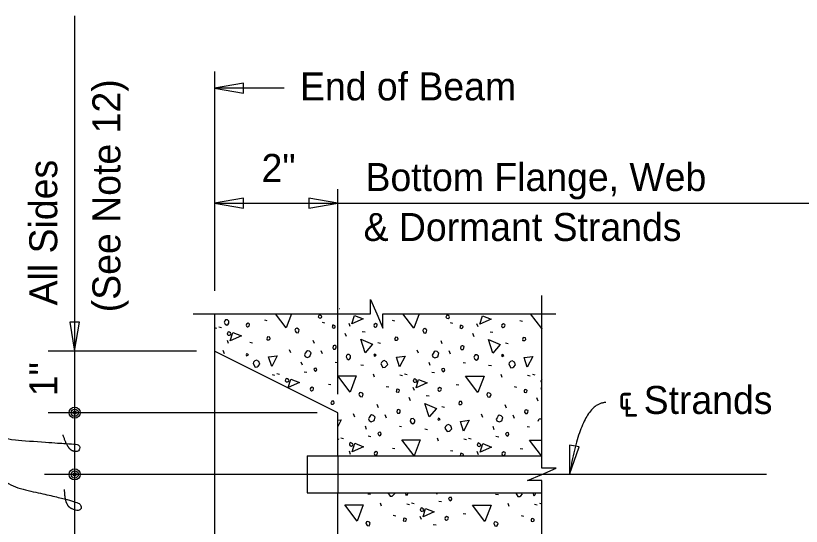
# Model space of a CAD drawing. Extents: x 0.5 to 29.5, y 0.9 to 17.7.
# Drawn here: x 2.752 to 7.001, y 2.834 to 5.592 of the extents above; entities that cross this region are included whole.
import ezdxf

# ---------------------------------------------------------------- set-up
doc = ezdxf.new("R2010")
doc.units = 0
for name, color, linetype in [('BeamConc', 7, 'Continuous'), ('BeamConc_h', 7, 'Continuous'), ('CL_Major', 7, 'Continuous'), ('Dimension', 7, 'Continuous'), ('Miscellaneous', 7, 'Continuous'), ('Rebar', 7, 'Continuous'), ('TextStructures', 7, 'Continuous')]:
    doc.layers.add(name, color=color, linetype=linetype)

msp = doc.modelspace()

# ---------------------------------------------------------------- linework, layer by layer
at = {"layer": 'BeamConc'}
for p, q in [((3.8274, 3.9817), (3.8274, 2.2462)), ((4.4941, 3.4472), (3.8274, 3.7806)), ((4.4941, 3.2139), (4.4941, 3.4472)), ((4.4941, 2.7806), (4.4941, 3.0139))]:
    msp.add_line(p, q, dxfattribs=at)
at = {"layer": 'BeamConc_h'}
msp.add_line((4.4941, 3.2139), (4.4941, 3.0139), dxfattribs=at)
at = {"layer": 'CL_Major'}
msp.add_line((6.8131, 3.1139), (2.9073, 3.1139), dxfattribs=at)
at = {"layer": 'Dimension'}
for p, q in [((3.0702, 5.5924), (3.0702, 2.0646)), ((3.8274, 5.2914), (3.8274, 4.1065)), ((4.2039, 5.2011), (3.8274, 5.2011)), ((4.4941, 3.5472), (4.4941, 4.6553)), ((3.8274, 4.5797), (7.089, 4.5797)), ((3.7295, 3.7806), (2.9278, 3.7806)), ((4.3815, 3.4472), (2.9278, 3.4472))]:
    msp.add_line(p, q, dxfattribs=at)
for points in [[(3.8273, 5.2012), (3.9835, 5.1747), (3.9835, 5.2276)], [(3.8273, 4.5797), (3.9835, 4.5532), (3.9835, 4.6062)], [(4.494, 4.5797), (4.3378, 4.6062), (4.3378, 4.5532)], [(3.0701, 3.7806), (3.0966, 3.9368), (3.0436, 3.9368)], [(5.7476, 3.1137), (5.7988, 3.2636), (5.7466, 3.2721)]]:
    msp.add_lwpolyline(points, close=True, dxfattribs=at)
for points in [[(5.5975, 2.1704), (5.5975, 3.0802), (5.52, 3.0802), (5.5975, 3.114), (5.675, 3.1477), (5.5975, 3.1477), (5.5975, 4.0806)], [(3.711, 3.9817), (4.6705, 3.9817), (4.6705, 4.0592), (4.7042, 3.9817), (4.738, 3.9042), (4.738, 3.9817), (5.6732, 3.9817)]]:
    msp.add_lwpolyline(points, dxfattribs=at)
for centre, radius in [((3.0707, 3.4475), 0.0299), ((3.0707, 3.4475), 0.0196), ((3.0707, 3.4475), 0.00888), ((3.0707, 3.1139), 0.0299), ((3.0707, 3.1139), 0.0196), ((3.0707, 3.1139), 0.00888)]:
    msp.add_circle(centre, radius, dxfattribs=at)
for points in [[(2.5377, 3.5116), (2.5377, 3.087), (3.0741, 2.9719), (3.1137, 2.9408), (3.0911, 2.9104), (3.0163, 2.9472), (3.0163, 3.0319)], [(5.9432, 3.5021), (5.8108, 3.5021), (5.7476, 3.1137)], [(2.538, 3.4819), (2.538, 3.3138), (3.0529, 3.2785), (3.1011, 3.2749), (3.0939, 3.2311), (3.0319, 3.248), (3.0079, 3.3286)]]:
    msp.add_open_spline(points, degree=2, dxfattribs=at)
at = {"layer": 'Miscellaneous'}
for p, q in [((4.5038, 4.0107), (4.5044, 4.0106)), ((3.8499, 3.9113), (3.864, 3.9078)), ((4.0965, 3.9487), (4.1098, 3.946)), ((4.4094, 3.9363), (4.4227, 3.9337)), ((4.5615, 3.9133), (4.5553, 3.9301)), ((4.7877, 3.9469), (4.801, 3.9443)), ((5.1006, 3.9346), (5.1139, 3.9319)), ((5.2527, 3.9116), (5.2465, 3.9284)), ((5.4789, 3.9452), (5.4922, 3.9425)), ((3.8243, 3.9069), (3.8384, 3.9033)), ((4.5402, 3.8585), (4.5332, 3.8762)), ((4.626, 3.8859), (4.6419, 3.8842)), ((5.2314, 3.8568), (5.2244, 3.8745)), ((5.3172, 3.8842), (5.3331, 3.8824)), ((3.9029, 3.8211), (3.8967, 3.8379)), ((4.0188, 3.8285), (4.0329, 3.825)), ((4.3679, 3.8205), (4.3608, 3.8382)), ((4.71, 3.8267), (4.7241, 3.8232)), ((5.0591, 3.8188), (5.052, 3.8364)), ((5.4012, 3.825), (5.4153, 3.8214)), ((3.8817, 3.7663), (3.8746, 3.784)), ((4.2397, 3.7702), (4.2327, 3.7878)), ((4.4112, 3.7649), (4.4041, 3.7825)), ((4.9309, 3.7684), (4.9239, 3.7861)), ((5.1024, 3.7631), (5.0953, 3.7808)), ((4.3025, 3.7039), (4.2963, 3.7207)), ((4.4801, 3.7207), (4.4925, 3.7189)), ((4.618, 3.7065), (4.6331, 3.7039)), ((4.9937, 3.7021), (4.9875, 3.7189)), ((5.1713, 3.7189), (5.1837, 3.7171)), ((5.3092, 3.7047), (5.3243, 3.7021)), ((4.1381, 3.6544), (4.1522, 3.6508)), ((4.1637, 3.6588), (4.1779, 3.6553)), ((4.3113, 3.6685), (4.3263, 3.6659)), ((4.6923, 3.6393), (4.6861, 3.6561)), ((4.8549, 3.657), (4.8691, 3.6535)), ((5.0025, 3.6667), (5.0175, 3.6641)), ((5.3835, 3.6376), (5.3773, 3.6544)), ((5.5461, 3.6553), (5.5602, 3.6517)), ((4.8293, 3.6526), (4.8434, 3.6491)), ((5.5205, 3.6508), (5.5346, 3.6473)), ((4.443, 3.6022), (4.4563, 3.5996)), ((4.7559, 3.5898), (4.7692, 3.5872)), ((4.9079, 3.5669), (4.9018, 3.5837)), ((5.1342, 3.6005), (5.1475, 3.5978)), ((5.4471, 3.5881), (5.4604, 3.5854)), ((5.5975, 3.5694), (5.593, 3.5819)), ((4.8867, 3.5121), (4.8797, 3.5297)), ((4.9725, 3.5395), (4.9884, 3.5377)), ((5.5779, 3.5103), (5.5709, 3.528)), ((4.7144, 3.4741), (4.7073, 3.4917)), ((5.4056, 3.4723), (5.3985, 3.49)), ((5.0564, 3.4802), (5.0706, 3.4767)), ((4.5862, 3.4237), (4.5791, 3.4414)), ((4.7577, 3.4184), (4.7506, 3.436)), ((5.2774, 3.4219), (5.2703, 3.4396)), ((5.4489, 3.4166), (5.4418, 3.4343)), ((4.649, 3.3574), (4.6428, 3.3742)), ((4.8266, 3.3742), (4.839, 3.3724)), ((4.9645, 3.36), (4.9795, 3.3574)), ((5.3402, 3.3556), (5.334, 3.3724)), ((5.5178, 3.3724), (5.5302, 3.3706)), ((4.6578, 3.322), (4.6728, 3.3194)), ((5.349, 3.3203), (5.364, 3.3176)), ((4.4941, 3.3055), (4.4987, 3.3044)), ((4.5102, 3.3123), (4.5243, 3.3088)), ((5.0388, 3.2929), (5.0326, 3.3097)), ((5.1758, 3.3061), (5.1899, 3.3026)), ((5.2014, 3.3105), (5.2155, 3.307)), ((4.5632, 3.2221), (4.557, 3.2389)), ((4.7895, 3.2557), (4.8028, 3.2531)), ((5.1024, 3.2434), (5.1157, 3.2407)), ((5.2544, 3.2204), (5.2482, 3.2372)), ((5.4807, 3.254), (5.494, 3.2513)), ((4.656, 3.0096), (4.671, 3.007)), ((5.0316, 3.0052), (5.0284, 3.0139)), ((5.3472, 3.0078), (5.3622, 3.0052)), ((4.7302, 2.9424), (4.724, 2.9592)), ((4.8672, 2.9557), (4.8814, 2.9522)), ((4.8929, 2.9601), (4.907, 2.9566)), ((5.0405, 2.9698), (5.0555, 2.9672)), ((5.4214, 2.9407), (5.4152, 2.9575)), ((5.5584, 2.9539), (5.5726, 2.9504)), ((5.584, 2.9583), (5.5976, 2.955)), ((4.4941, 2.9027), (4.4942, 2.9027)), ((4.7939, 2.8929), (4.8071, 2.8903)), ((5.1722, 2.9035), (5.1854, 2.9009)), ((5.4851, 2.8912), (5.4983, 2.8885)), ((4.9459, 2.87), (4.9397, 2.8868)), ((5.0104, 2.8426), (5.0263, 2.8408))]:
    msp.add_line(p, q, dxfattribs=at)
for points in [[(4.2141, 3.9054), (4.1561, 3.9817)], [(4.2426, 3.9817), (4.2141, 3.9054)], [(4.393, 3.9593), (4.3992, 3.9584), (4.4054, 3.9611), (4.4072, 3.9664), (4.4045, 3.9708), (4.3992, 3.9743), (4.393, 3.977), (4.3895, 3.9699), (4.3877, 3.9646), (4.393, 3.9593)], [(4.5703, 3.9275), (4.5844, 3.9734), (4.6313, 3.9549), (4.5703, 3.9275)], [(4.9053, 3.9036), (4.846, 3.9817)], [(4.9345, 3.9817), (4.9053, 3.9036)], [(5.0842, 3.9575), (5.0904, 3.9567), (5.0966, 3.9593), (5.0984, 3.9646), (5.0957, 3.969), (5.0904, 3.9726), (5.0842, 3.9752), (5.0807, 3.9681), (5.0789, 3.9628), (5.0842, 3.9575)], [(5.2615, 3.9257), (5.2756, 3.9717), (5.3225, 3.9531), (5.2615, 3.9257)], [(5.5965, 3.9019), (5.5358, 3.9817)], [(3.88, 3.9364), (3.8853, 3.9258), (3.8941, 3.9205), (3.9012, 3.9258), (3.9047, 3.9311), (3.9047, 3.9417), (3.8967, 3.9497), (3.887, 3.9488), (3.8826, 3.9444), (3.88, 3.9364)], [(4.0028, 3.9116), (4.0064, 3.9116), (4.0135, 3.9151), (4.0161, 3.9231), (4.0152, 3.9275), (4.0081, 3.931), (3.9993, 3.9257), (3.9975, 3.9204), (3.9993, 3.9151), (4.0028, 3.9116)], [(4.4633, 3.9072), (4.4731, 3.9045), (4.4793, 3.9089), (4.4801, 3.9151), (4.4784, 3.9169), (4.4713, 3.9204), (4.4651, 3.9195), (4.4642, 3.9133), (4.4633, 3.9072)], [(4.694, 3.9098), (4.6976, 3.9098), (4.7047, 3.9133), (4.7073, 3.9213), (4.7064, 3.9257), (4.6993, 3.9293), (4.6905, 3.924), (4.6887, 3.9186), (4.6905, 3.9133), (4.694, 3.9098)], [(5.1545, 3.9054), (5.1643, 3.9027), (5.1705, 3.9072), (5.1713, 3.9133), (5.1696, 3.9151), (5.1625, 3.9186), (5.1563, 3.9178), (5.1554, 3.9116), (5.1545, 3.9054)], [(5.3852, 3.908), (5.3888, 3.908), (5.3958, 3.9116), (5.3985, 3.9195), (5.3976, 3.924), (5.3905, 3.9275), (5.3817, 3.9222), (5.3799, 3.9169), (5.3817, 3.9116), (5.3852, 3.908)], [(3.9012, 3.8671), (3.9074, 3.8662), (3.9135, 3.8689), (3.9153, 3.8742), (3.9127, 3.8786), (3.9074, 3.8821), (3.9012, 3.8848), (3.8976, 3.8777), (3.8959, 3.8724), (3.9012, 3.8671)], [(3.9118, 3.8353), (3.9259, 3.8812), (3.9728, 3.8627), (3.9118, 3.8353)], [(4.2636, 3.8895), (4.268, 3.8815), (4.2786, 3.8798), (4.283, 3.8877), (4.2848, 3.8948), (4.2804, 3.8992), (4.2724, 3.9036), (4.2645, 3.901), (4.2618, 3.893), (4.2636, 3.8895)], [(4.9548, 3.8877), (4.9592, 3.8798), (4.9698, 3.878), (4.9742, 3.8859), (4.976, 3.893), (4.9716, 3.8974), (4.9636, 3.9019), (4.9557, 3.8992), (4.953, 3.8912), (4.9548, 3.8877)], [(5.5976, 3.9047), (5.5965, 3.9019)], [(4.1124, 3.8409), (4.1231, 3.8409), (4.1284, 3.8462), (4.1257, 3.8559), (4.1142, 3.8568), (4.1124, 3.8515), (4.1098, 3.8471), (4.1124, 3.8409), (4.1107, 3.8426)], [(4.6419, 3.771), (4.618, 3.8444), (4.6808, 3.817), (4.6419, 3.771)], [(4.8036, 3.8391), (4.8143, 3.8391), (4.8196, 3.8444), (4.8169, 3.8541), (4.8054, 3.855), (4.8036, 3.8497), (4.801, 3.8453), (4.8036, 3.8391), (4.8019, 3.8409)], [(5.3331, 3.7693), (5.3092, 3.8426), (5.372, 3.8152), (5.3331, 3.7693)], [(5.4948, 3.8373), (5.5054, 3.8373), (5.5108, 3.8426), (5.5081, 3.8524), (5.4966, 3.8532), (5.4948, 3.8479), (5.4922, 3.8435), (5.4948, 3.8373), (5.4931, 3.8391)], [(4.3166, 3.7516), (4.3281, 3.7454), (4.3431, 3.7516), (4.3493, 3.7702), (4.3405, 3.779), (4.329, 3.7816), (4.3237, 3.7781), (4.3175, 3.7684), (4.3131, 3.7604), (4.3166, 3.7516)], [(4.466, 3.7984), (4.4704, 3.7905), (4.4801, 3.7914), (4.4846, 3.7976), (4.4854, 3.8073), (4.4793, 3.8099), (4.4748, 3.8108), (4.4695, 3.809), (4.4678, 3.8073), (4.466, 3.7984)], [(5.1572, 3.7967), (5.1616, 3.7887), (5.1713, 3.7896), (5.1758, 3.7958), (5.1766, 3.8055), (5.1705, 3.8082), (5.166, 3.809), (5.1607, 3.8073), (5.159, 3.8055), (5.1572, 3.7967)], [(4.0002, 3.7551), (4.0099, 3.7596), (4.0064, 3.7631), (4.0002, 3.7657), (3.9975, 3.7596), (4.0002, 3.7551)], [(4.1363, 3.6968), (4.1195, 3.7489), (4.1664, 3.7551), (4.1363, 3.6968)], [(4.5385, 3.7489), (4.5438, 3.7383), (4.5526, 3.733), (4.5597, 3.7383), (4.5632, 3.7436), (4.5632, 3.7542), (4.5553, 3.7622), (4.5456, 3.7613), (4.5411, 3.7569), (4.5385, 3.7489)], [(4.6914, 3.7534), (4.7011, 3.7578), (4.6976, 3.7613), (4.6914, 3.764), (4.6887, 3.7578), (4.6914, 3.7534)], [(4.8275, 3.695), (4.8107, 3.7472), (4.8576, 3.7534), (4.8275, 3.695)], [(5.0078, 3.7498), (5.0193, 3.7436), (5.0343, 3.7498), (5.0405, 3.7684), (5.0317, 3.7772), (5.0202, 3.7799), (5.0149, 3.7763), (5.0087, 3.7666), (5.0043, 3.7587), (5.0078, 3.7498)], [(5.2297, 3.7472), (5.235, 3.7366), (5.2438, 3.7313), (5.2509, 3.7366), (5.2544, 3.7419), (5.2544, 3.7525), (5.2465, 3.7604), (5.2367, 3.7596), (5.2323, 3.7551), (5.2297, 3.7472)], [(5.3826, 3.7516), (5.3923, 3.756), (5.3888, 3.7596), (5.3826, 3.7622), (5.3799, 3.756), (5.3826, 3.7516)], [(5.5187, 3.6933), (5.5019, 3.7454), (5.5488, 3.7516), (5.5187, 3.6933)], [(4.0356, 3.7127), (4.047, 3.6941), (4.0585, 3.695), (4.063, 3.6994), (4.0727, 3.7092), (4.0665, 3.7242), (4.0541, 3.7313), (4.0453, 3.7277), (4.0382, 3.7207), (4.0356, 3.7127)], [(4.7267, 3.7109), (4.7382, 3.6924), (4.7497, 3.6933), (4.7541, 3.6977), (4.7639, 3.7074), (4.7577, 3.7224), (4.7453, 3.7295), (4.7365, 3.726), (4.7294, 3.7189), (4.7267, 3.7109)], [(5.4179, 3.7092), (5.4294, 3.6906), (5.4409, 3.6915), (5.4453, 3.6959), (5.4551, 3.7056), (5.4489, 3.7207), (5.4365, 3.7277), (5.4277, 3.7242), (5.4206, 3.7171), (5.4179, 3.7092)], [(4.367, 3.6747), (4.3723, 3.6694), (4.3776, 3.6729), (4.3811, 3.6782), (4.3794, 3.6871), (4.375, 3.688), (4.3688, 3.6871), (4.3635, 3.6818), (4.367, 3.6747)], [(5.0582, 3.6729), (5.0635, 3.6676), (5.0688, 3.6712), (5.0723, 3.6765), (5.0706, 3.6853), (5.0662, 3.6862), (5.06, 3.6853), (5.0547, 3.68), (5.0582, 3.6729)], [(4.215, 3.6146), (4.2212, 3.6137), (4.2274, 3.6164), (4.2291, 3.6217), (4.2265, 3.6261), (4.2212, 3.6296), (4.215, 3.6323), (4.2114, 3.6252), (4.2097, 3.6199), (4.215, 3.6146)], [(4.2256, 3.5828), (4.2397, 3.6287), (4.2866, 3.6102), (4.2256, 3.5828)], [(4.5606, 3.5589), (4.4934, 3.6473), (4.5933, 3.6464), (4.5606, 3.5589)], [(4.9062, 3.6128), (4.9124, 3.6119), (4.9185, 3.6146), (4.9203, 3.6199), (4.9177, 3.6243), (4.9124, 3.6279), (4.9062, 3.6305), (4.9026, 3.6234), (4.9009, 3.6181), (4.9062, 3.6128)], [(4.9168, 3.581), (4.9309, 3.627), (4.9778, 3.6084), (4.9168, 3.581)], [(5.2518, 3.5571), (5.1846, 3.6455), (5.2845, 3.6446), (5.2518, 3.5571)], [(5.5975, 3.6287), (5.5974, 3.6287), (5.5938, 3.6217), (5.5921, 3.6164), (5.5974, 3.6111)], [(4.3493, 3.5651), (4.3529, 3.5651), (4.3599, 3.5686), (4.3626, 3.5766), (4.3617, 3.581), (4.3546, 3.5845), (4.3458, 3.5792), (4.344, 3.5739), (4.3458, 3.5686), (4.3493, 3.5651)], [(4.8098, 3.5607), (4.8196, 3.558), (4.8257, 3.5624), (4.8266, 3.5686), (4.8249, 3.5704), (4.8178, 3.5739), (4.8116, 3.5731), (4.8107, 3.5669), (4.8098, 3.5607)], [(5.0405, 3.5633), (5.0441, 3.5633), (5.0511, 3.5669), (5.0538, 3.5748), (5.0529, 3.5792), (5.0458, 3.5828), (5.037, 3.5775), (5.0352, 3.5722), (5.037, 3.5669), (5.0405, 3.5633)], [(5.501, 3.5589), (5.5108, 3.5563), (5.5169, 3.5607), (5.5178, 3.5669), (5.5161, 3.5686), (5.509, 3.5722), (5.5028, 3.5713), (5.5019, 3.5651), (5.501, 3.5589)], [(5.5974, 3.6111), (5.5975, 3.611)], [(4.6101, 3.543), (4.6145, 3.535), (4.6251, 3.5333), (4.6295, 3.5412), (4.6313, 3.5483), (4.6269, 3.5527), (4.6189, 3.5571), (4.611, 3.5545), (4.6083, 3.5465), (4.6101, 3.543)], [(5.3013, 3.5412), (5.3057, 3.5333), (5.3163, 3.5315), (5.3207, 3.5395), (5.3225, 3.5465), (5.3181, 3.551), (5.3101, 3.5554), (5.3022, 3.5527), (5.2995, 3.5448), (5.3013, 3.5412)], [(4.4589, 3.4944), (4.4695, 3.4944), (4.4748, 3.4997), (4.4722, 3.5094), (4.4607, 3.5103), (4.4589, 3.505), (4.4563, 3.5006), (4.4589, 3.4944), (4.4572, 3.4962)], [(4.9884, 3.4246), (4.9645, 3.4979), (5.0273, 3.4705), (4.9884, 3.4246)], [(5.1501, 3.4926), (5.1607, 3.4926), (5.166, 3.4979), (5.1634, 3.5076), (5.1519, 3.5085), (5.1501, 3.5032), (5.1475, 3.4988), (5.1501, 3.4926), (5.1484, 3.4944)], [(4.8125, 3.452), (4.8169, 3.444), (4.8266, 3.4449), (4.831, 3.4511), (4.8319, 3.4608), (4.8257, 3.4634), (4.8213, 3.4643), (4.816, 3.4626), (4.8143, 3.4608), (4.8125, 3.452)], [(5.5037, 3.4502), (5.5081, 3.4422), (5.5178, 3.4431), (5.5222, 3.4493), (5.5231, 3.459), (5.5169, 3.4617), (5.5125, 3.4626), (5.5072, 3.4608), (5.5054, 3.459), (5.5037, 3.4502)], [(4.4941, 3.4062), (4.5128, 3.4086), (4.4941, 3.3722)], [(4.6631, 3.4051), (4.6746, 3.3989), (4.6896, 3.4051), (4.6958, 3.4237), (4.687, 3.4325), (4.6755, 3.4352), (4.6702, 3.4316), (4.664, 3.4219), (4.6596, 3.414), (4.6631, 3.4051)], [(4.885, 3.4025), (4.8903, 3.3919), (4.8991, 3.3866), (4.9062, 3.3919), (4.9097, 3.3972), (4.9097, 3.4078), (4.9018, 3.4157), (4.892, 3.4148), (4.8876, 3.4104), (4.885, 3.4025)], [(5.0379, 3.4069), (5.0476, 3.4113), (5.0441, 3.4148), (5.0379, 3.4175), (5.0352, 3.4113), (5.0379, 3.4069)], [(5.174, 3.3485), (5.1572, 3.4007), (5.204, 3.4069), (5.174, 3.3485)], [(5.3543, 3.4033), (5.3658, 3.3972), (5.3808, 3.4033), (5.387, 3.4219), (5.3782, 3.4307), (5.3667, 3.4334), (5.3614, 3.4299), (5.3552, 3.4201), (5.3508, 3.4122), (5.3543, 3.4033)], [(5.5975, 3.4094), (5.593, 3.414), (5.5832, 3.4131), (5.5788, 3.4086), (5.5762, 3.4007)], [(5.0732, 3.3645), (5.0847, 3.3459), (5.0962, 3.3468), (5.1006, 3.3512), (5.1104, 3.3609), (5.1042, 3.3759), (5.0918, 3.383), (5.083, 3.3795), (5.0759, 3.3724), (5.0732, 3.3645)], [(4.7135, 3.3282), (4.7188, 3.3229), (4.7241, 3.3264), (4.7276, 3.3318), (4.7259, 3.3406), (4.7214, 3.3415), (4.7153, 3.3406), (4.71, 3.3353), (4.7135, 3.3282)], [(5.4047, 3.3264), (5.41, 3.3211), (5.4153, 3.3247), (5.4188, 3.33), (5.4171, 3.3388), (5.4126, 3.3397), (5.4065, 3.3388), (5.4012, 3.3335), (5.4047, 3.3264)], [(4.5615, 3.2681), (4.5676, 3.2672), (4.5738, 3.2699), (4.5756, 3.2752), (4.573, 3.2796), (4.5676, 3.2831), (4.5615, 3.2858), (4.5579, 3.2787), (4.5562, 3.2734), (4.5615, 3.2681)], [(4.5721, 3.2363), (4.5862, 3.2823), (4.6331, 3.2637), (4.5721, 3.2363)], [(4.9059, 3.2139), (4.8399, 3.3008), (4.9398, 3.2999), (4.9076, 3.2139)], [(5.2527, 3.2663), (5.2588, 3.2655), (5.265, 3.2681), (5.2668, 3.2734), (5.2641, 3.2778), (5.2588, 3.2814), (5.2527, 3.284), (5.2491, 3.2769), (5.2474, 3.2716), (5.2527, 3.2663)], [(5.2633, 3.2345), (5.2774, 3.2805), (5.3243, 3.2619), (5.2633, 3.2345)], [(5.5958, 3.2139), (5.5311, 3.299), (5.5975, 3.2985)], [(4.6958, 3.2186), (4.6993, 3.2186), (4.7064, 3.2221), (4.7091, 3.2301), (4.7082, 3.2345), (4.7011, 3.2381), (4.6923, 3.2328), (4.6905, 3.2275), (4.6923, 3.2221), (4.6958, 3.2186)], [(5.387, 3.2168), (5.3905, 3.2168), (5.3976, 3.2204), (5.4003, 3.2283), (5.3994, 3.2328), (5.3923, 3.2363), (5.3835, 3.231), (5.3817, 3.2257), (5.3835, 3.2204), (5.387, 3.2168)], [(5.1694, 3.2139), (5.1722, 3.216), (5.1731, 3.2221), (5.1713, 3.2239), (5.1643, 3.2275), (5.1581, 3.2266), (5.1572, 3.2204), (5.1563, 3.2142)], [(5.1563, 3.2142), (5.1572, 3.2139)], [(4.7647, 3.0139), (4.7762, 2.9955), (4.7877, 2.9964), (4.7921, 3.0008), (4.8018, 3.0105), (4.8004, 3.0139)], [(4.8654, 2.9981), (4.8604, 3.0139)], [(4.8736, 3.0139), (4.8654, 2.9981)], [(5.0961, 2.976), (5.1014, 2.9707), (5.1067, 2.9743), (5.1103, 2.9796), (5.1085, 2.9884), (5.1041, 2.9893), (5.0979, 2.9884), (5.0926, 2.9831), (5.0961, 2.976)], [(5.4559, 3.0123), (5.4674, 2.9937), (5.4789, 2.9946), (5.4833, 2.999), (5.493, 3.0087), (5.4909, 3.0139)], [(5.4564, 3.0139), (5.4559, 3.0123)], [(5.5566, 2.9964), (5.551, 3.0139)], [(5.5657, 3.0139), (5.5566, 2.9964)], [(4.5985, 2.862), (4.5313, 2.9504), (4.6312, 2.9495), (4.5985, 2.862)], [(4.9441, 2.9159), (4.9503, 2.915), (4.9565, 2.9177), (4.9583, 2.923), (4.9556, 2.9274), (4.9503, 2.9309), (4.9441, 2.9336), (4.9406, 2.9265), (4.9388, 2.9212), (4.9441, 2.9159)], [(5.2897, 2.8602), (5.2225, 2.9486), (5.3224, 2.9477), (5.2897, 2.8602)], [(4.9547, 2.8841), (4.9689, 2.9301), (5.0157, 2.9115), (4.9547, 2.8841)], [(4.648, 2.8461), (4.6524, 2.8381), (4.663, 2.8364), (4.6675, 2.8443), (4.6692, 2.8514), (4.6648, 2.8558), (4.6569, 2.8602), (4.6489, 2.8576), (4.6462, 2.8496), (4.648, 2.8461)], [(4.8478, 2.8638), (4.8575, 2.8611), (4.8637, 2.8655), (4.8646, 2.8717), (4.8628, 2.8735), (4.8557, 2.877), (4.8495, 2.8761), (4.8487, 2.87), (4.8478, 2.8638)], [(5.0785, 2.8664), (5.082, 2.8664), (5.0891, 2.87), (5.0917, 2.8779), (5.0908, 2.8823), (5.0838, 2.8859), (5.0749, 2.8806), (5.0732, 2.8753), (5.0749, 2.87), (5.0785, 2.8664)], [(5.3392, 2.8443), (5.3436, 2.8364), (5.3542, 2.8346), (5.3587, 2.8426), (5.3604, 2.8496), (5.356, 2.854), (5.3481, 2.8585), (5.3401, 2.8558), (5.3374, 2.8479), (5.3392, 2.8443)], [(5.539, 2.862), (5.5487, 2.8594), (5.5549, 2.8638), (5.5558, 2.87), (5.554, 2.8717), (5.5469, 2.8753), (5.5407, 2.8744), (5.5399, 2.8682), (5.539, 2.862)]]:
    msp.add_lwpolyline(points, dxfattribs=at)
at = {"layer": 'Rebar'}
for p, q in [((4.3274, 3.2139), (5.5975, 3.2139)), ((4.3274, 3.2139), (4.3274, 3.0139)), ((4.3274, 3.0139), (5.5975, 3.0139))]:
    msp.add_line(p, q, dxfattribs=at)

# ---------------------------------------------------------------- texts
at = {"layer": 'TextStructures'}
for s, p in [('End of Beam', (4.2892, 5.1349)), ('2" ', (4.0815, 4.6945)), (' Bottom Flange, Web ', (4.5876, 4.6451)), ('& Dormant Strands', (4.6332, 4.3753)), ('℄ Strands', (6.0099, 3.4407))]:
    msp.add_text(s, height=0.1512, dxfattribs=at).set_placement(p)
for s, p in [('(See Note 12)', (3.3178, 3.9901)), ('All Sides', (2.9762, 4.0272)), ('1"  ', (2.9762, 3.5362))]:
    msp.add_text(s, height=0.1512, rotation=90, dxfattribs=at).set_placement(p)

doc.saveas('drawing.dxf')
